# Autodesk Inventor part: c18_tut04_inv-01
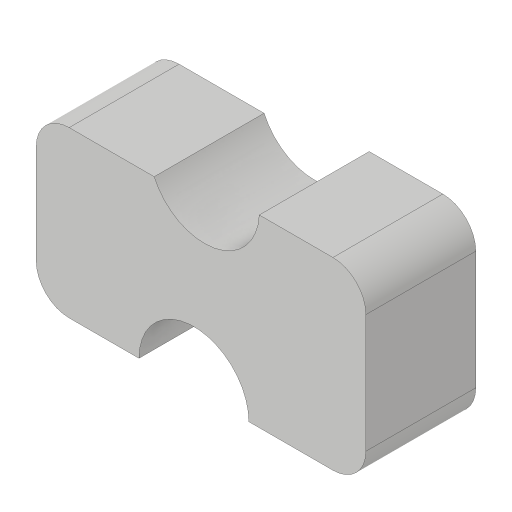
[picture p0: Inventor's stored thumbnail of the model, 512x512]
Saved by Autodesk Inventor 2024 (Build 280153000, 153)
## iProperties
Created: 2017-06
Part Number: c18_tut04_inv-01
Material: Generic
Document SubType Name: Modeling
Designer: CADCIM 00
Density: 1 g/cm^3
Appearance: Default
Author: CADCIM 00
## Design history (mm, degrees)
sketch "Sketch1"
  geometry: L1 (-60, 0)-(-60, 33.532); L2 (0, 30)-(0, 0); L3 (-60, 33.532)-(-40.6, 33.532); L4 (-21.474, 30)-(0, 30); L5 (0, 0)-(-18.704, 0); L6 (-38.704, 0)-(-60, 0); A1 r 10 centre (-30.614, 34.057) between (-40.6, 33.532) and (-21.474, 30); A2 r 10 centre (-28.704, 0) between (-18.704, 0) and (-38.704, 0)
  constraints: 12 end point, 5 parallel, 4 point on circle, 2 centre point, 2 horizontal, 2 perpendicular, 1 equal radius
  dimensions: "d0" = 60 distance between parallel lines of L1 L2 (= LEN); "d1" = 30 distance of L2.start L2.end (= WID); "d2" = 10 radius of A2 (= RAD)
extrude "Extrusion1" new body sketch "Sketch1" distance "d3" = 20 (= EXT); taper "d4" = 0 deg
fillet "Fillet1" dims "d5" = 6 (= FILLET)
body "Solid1"
other parameters: "LEN" = 60 [user parameter; used in 5 equation terms], "WID" = 30 (= 0.5 x LEN) [user parameter; used in 1 equation term], "RAD" = 10 (= 0.166667 x LEN) [user parameter; used in 1 equation term], "EXT" = 20 (= 0.333333 x LEN) [user parameter; used in 1 equation term], "FILLET" = 6 (= 0.1 x LEN) [user parameter; used in 1 equation term]
